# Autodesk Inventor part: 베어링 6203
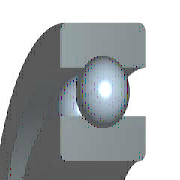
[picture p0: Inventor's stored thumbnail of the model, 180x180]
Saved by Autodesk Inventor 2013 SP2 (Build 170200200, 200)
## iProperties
IsCustomPart: 1
Created: 2015-09
Part Number: 베어링 6203
Material: 강철, 연강
Description: 깊은 그루브 볼 베어링
Document SubType Name: Modeling
Standard: KS B 2023
Standards Organization: KS
Language: ko-KR
Size Designation: 6203 - 17 x 40 x 12
Categories: <MemberInstance><Categories><Category DisplayName="샤프트 부품" InternalName="7f7aeb1f-a693-4053-b835-cee3144e0d98" Mnemonic="SHFT"><Category DisplayName="베어링" Inter
Density: 7.86 g/cm^3
Mass: 64.9809 g
Surface Area: 64.3582 cm^2
Volume: 8.26729 cm^3
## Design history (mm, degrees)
sketch "스케치" dims "d0" = 5.98 (= -0.26 x WD + 0.26 x BD)
  geometry: L1 (3.01, 14.25)-(8.99, 14.25); L2 (6, 14.25)-(6, 11.26); L3 (6, 14.25)-(6, 17.24); L4 (3.778, 12.249)-(0, 12.249); L5 (0, 8.5)-(12, 8.5); L6 (3.778, 16.251)-(0, 16.251); L7 (0, 20)-(12, 20); L8 (12, 8.5)-(12, 12.249); L9 (8.222, 12.249)-(12, 12.249); L10 (8.222, 16.251)-(12, 16.251); L11 (12, 20)-(12, 16.251); L12 (-1.4, 0)-(8.4, 0) reference; L13 (0, -0.3)-(0, 5.3) reference
  constraints: 22 end point, 4 point on line, 2 collinear, 2 perpendicular, 2 symmetric about line, 1 midpoint, 1 parallel, 14 other
  dimensions: "d9" = 17 diameter of L5 L12 (= WD); "d11" = 40 diameter of L7 L12 (= BD); "d12" = 12 distance between parallel lines of L8 L13 (= KB); "d13" = 24.498 diameter of L9 L12 (= 0.326 x BD + 0.674 x WD)
revolve "본체" stored, may be unused: angle "d6" = 90 deg
revolve "볼" stored, may be unused: angle "d7" = 90 deg
pattern_circular "IDS_ARRAYBALL[SIMPL:T]" dims angle "d3" = 360 deg
body "Solid1"
fillet "모깎기1" dims "d1" = 0.6 (= KRS)
other parameters: "WD" = 17 [user parameter; used in 5 equation terms], "BD" = 40 [user parameter; used in 5 equation terms], "KB" = 12 [user parameter; used in 1 equation term], "KRS" = 0.6 [user parameter; used in 1 equation term], "d4" = 0, "d5" = 0, "d8" = 0, "d14" = 0, "d15" = 0, "BBA" = 0 [user parameter], "BC0" = 4750000 [user parameter], "BC" = 9560000 [user parameter], "WR" = 8.5 (= 0.5 x WD) [user parameter]
